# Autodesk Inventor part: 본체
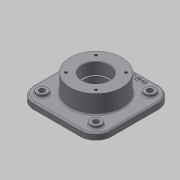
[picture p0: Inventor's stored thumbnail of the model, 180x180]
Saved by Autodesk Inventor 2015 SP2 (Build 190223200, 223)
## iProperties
Created: 2015-07
Part Number: 본체
Material: 일반
Document SubType Name: Modeling
Designer: AMC
Density: 1 g/cm^3
Appearance: 기본값
Author: AMC
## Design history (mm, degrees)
sketch "스케치1"
  geometry: L1 (-75, -75)-(75, -75); L2 (75, -75)-(75, 75); L3 (75, 75)-(-75, 75); L4 (-75, 75)-(-75, -75); L5 (-75, -75)-(75, 75); L6 (75, -75)-(-75, 75); 1 further point
  constraints: 12 end point, 2 midpoint, 2 parallel, 1 horizontal, 1 perpendicular
  dimensions: "d0" = 150 distance of L3.end L2.end; "d1" = 150 distance of L2.end L1.end
extrude "돌출1" new body sketch "스케치1" distance "d2" = 12; taper "d3" = 0 deg
sketch "스케치2"
  geometry: C1 r 50 at (0, 0); 1 further point
  constraints: 1 centre point, 1 coincident
  dimensions: "d4" = 100 diameter of C1
extrude "돌출2" join sketch "스케치2" stored distance "d5" = 70; taper "d6" = 0 deg
hole "구멍1" diameter "d9" = 45; stored, may be unused: countersink angle "d13" = 90 deg, drill point angle "d15" = 0 deg; dims "d7" = 10, "d8" = 10, "d10" = 6, "d11" = 52, "d12" = 22, "d14" = 35
hole "구멍2" diameter "d18" = 45; stored, may be unused: countersink angle "d22" = 90 deg, drill point angle "d24" = 0 deg; dims "d16" = 10, "d17" = 10, "d19" = 6, "d20" = 52, "d21" = 22, "d23" = 35
sketch "스케치3"
  geometry: L1 (0, 0)-(41, 0); L2 (0, 0)-(28.991, -28.991); A1 r 41 centre (0, 0) between (41, 0) and (28.991, -28.991); 1 further point
  constraints: 4 end point, 2 point on circle, 1 centre point, 1 coincident, 1 horizontal
  dimensions: "d25" = 82 diameter of A1; "d26" = 45 deg angle of L2 L1
hole "구멍3" sketch "스케치3" at (28.991, -28.991) diameter "d27" = 4.917; stored, may be unused: countersink angle "d31" = 90 deg, drill point angle "d33" = 118 deg; dims "d28" = 10, "d29" = 52, "d30" = 22, "d32" = 13
sketch "스케치4"
  geometry: L1 (0, 0)-(41, 0); L2 (0, 0)-(28.991, -28.991); A1 r 41 centre (0, 0) between (41, 0) and (28.991, -28.991); 1 further point
  constraints: 4 end point, 2 point on circle, 1 centre point, 1 coincident, 1 horizontal
  dimensions: "d37" = 82 diameter of A1; "d38" = 45 deg angle of L2 L1
hole "구멍4" sketch "스케치4" at (28.991, -28.991) diameter "d39" = 4.917; stored, may be unused: countersink angle "d43" = 90 deg, drill point angle "d45" = 118 deg; dims "d40" = 10, "d41" = 52, "d42" = 22, "d44" = 13
sketch "스케치6"
  geometry: L1 (75, 75)-(-75, 75) reference; L2 (-75, 75)-(-75, -75) reference; L3 (-75, -75)-(75, -75) reference; L4 (75, -75)-(75, 75) reference; C1 r 10 at (-52, 52); C2 r 10 at (52, 52); C3 r 10 at (52, -52); C4 r 10 at (-52, -52); 1 further point
  constraints: 4 centre point
  dimensions: "d72" = 20 diameter of C1; "d73" = 20 diameter of C2; "d74" = 20 diameter of C3; "d75" = 20 diameter of C4; "d76" = 23 distance from line of C1.centre L1; "d77" = 23 distance from line of L2 C1.centre; "d78" = 23 distance from line of C4.centre L2; "d79" = 23 distance from line of L3 C4.centre; "d80" = 23 distance from line of L4 C3.centre; "d81" = 23 distance from line of L3 C3.centre; "d82" = 23 distance from line of C2.centre L1; "d83" = 23 distance from line of C2.centre L4
extrude "돌출4" join sketch "스케치6" distance "d84" = 5; taper "d85" = 0 deg
hole "구멍6" diameter "d88" = 11; stored, may be unused: countersink angle "d92" = 90 deg, drill point angle "d94" = 0 deg; dims "d86" = 10, "d87" = 10, "d89" = 10, "d90" = 52, "d91" = 22, "d93" = 50
hole "구멍7" diameter "d97" = 11; stored, may be unused: countersink angle "d101" = 90 deg, drill point angle "d103" = 0 deg; dims "d95" = 10, "d96" = 10, "d98" = 10, "d99" = 52, "d100" = 22, "d102" = 50
hole "구멍8" diameter "d106" = 11; stored, may be unused: countersink angle "d110" = 90 deg, drill point angle "d112" = 0 deg; dims "d104" = 10, "d105" = 10, "d107" = 10, "d108" = 52, "d109" = 22, "d111" = 50
hole "구멍9" diameter "d115" = 11; stored, may be unused: countersink angle "d119" = 90 deg, drill point angle "d121" = 0 deg; dims "d113" = 10, "d114" = 10, "d116" = 10, "d117" = 52, "d118" = 22, "d120" = 50
fillet "모깎기1" dims "d122" = 2
fillet "모깎기2" dims "d123" = 30
fillet "모깎기4" dims "d125" = 0.3
chamfer "모따기1" distance "d126" = 1; stored, may be unused: second distance "d127" = 2, angle "d128" = 45 deg
sketch "스케치7"
  geometry: 2 further points
  constraints: 1 vertical alignment, 1 other
  dimensions: "d129" = 65 distance of point (0, 0) point (0, 65)
fillet "모깎기5" dims "d130" = 3
fillet "모깎기6" dims "d131" = 3
node "솔리드1"
pattern_circular "원형 패턴1" dims angle "d35" = 360 deg
pattern_circular "원형 패턴2" dims angle "d47" = 360 deg
